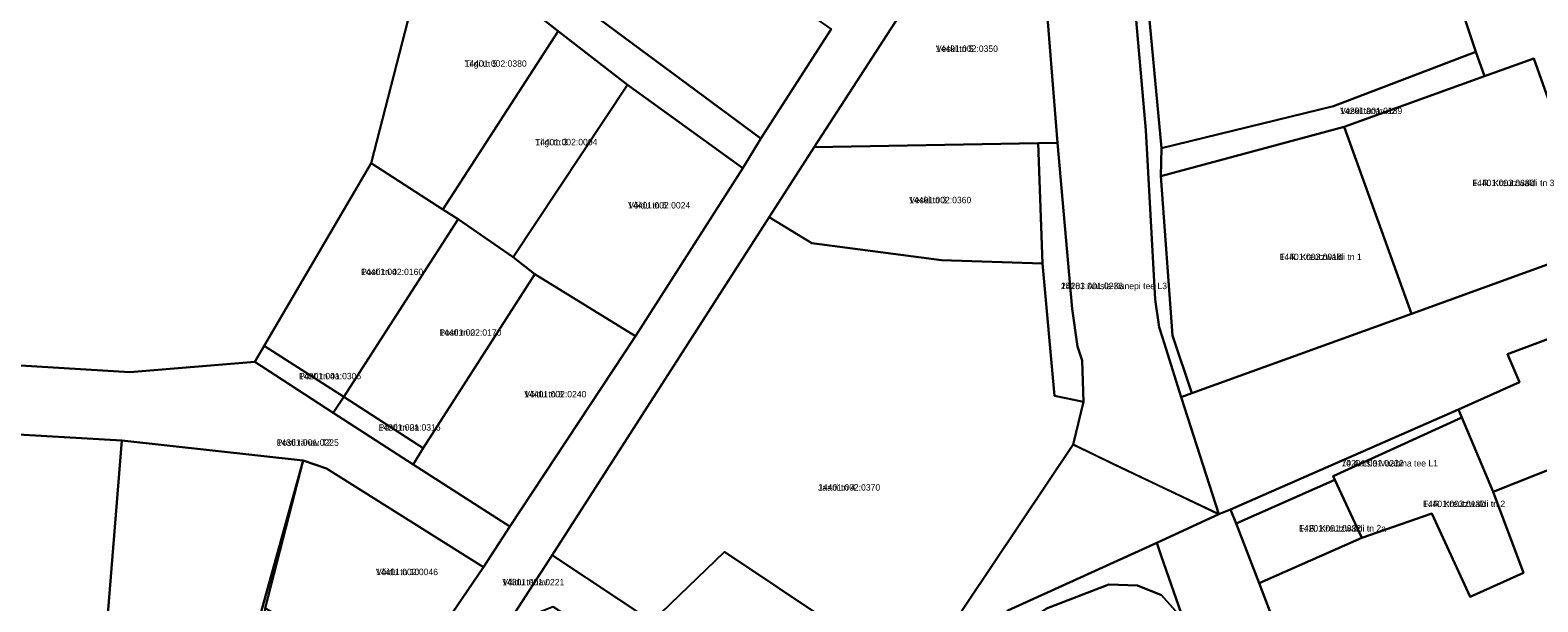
# Model space of a CAD drawing. Extents: x 640657 to 665127, y 6395726 to 6426831.
# Drawn here: x 649927.6 to 650279.7, y 6412496.8 to 6412630.2 of the extents above; entities that cross this region are included whole.
import ezdxf

# ---------------------------------------------------------------- set-up
doc = ezdxf.new("R2010")
doc.units = 0
for name, color, linetype in [('L_AADRESS', 7, 'Continuous'), ('PIIR', 7, 'Continuous'), ('TUNNUS', 7, 'Continuous')]:
    doc.layers.add(name, color=color, linetype=linetype)

msp = doc.modelspace()

# ---------------------------------------------------------------- linework, layer by layer
at = {"layer": 'PIIR'}
for points in [[(650237.63, 6412705.98), (650303.88, 6412730.75), (650316.1, 6412701.52), (650316.75, 6412691.86), (650305.68, 6412683.87), (650314.59, 6412660.95), (650328.64, 6412621.96), (650285.03, 6412605.8), (650278.75, 6412623.58), (650267.2, 6412619.43), (650265.16, 6412625.12), (650252.6, 6412662.9)], [(650196.38, 6412544.58), (650192.03, 6412558.48), (650191.24, 6412560.88), (650190.3, 6412567.31), (650188.12, 6412606.82), (650184.85, 6412644.1), (650184.49, 6412647.84), (650182.46, 6412660.87), (650180.97, 6412664.81), (650176.35, 6412683.53), (650172.79, 6412698.44), (650170.66, 6412706.52), (650172.47, 6412706.22), (650178.71, 6412684.02), (650184.97, 6412661.12), (650188.11, 6412641.75), (650191.8, 6412602.62), (650191.64, 6412596.08), (650194.33, 6412558.97), (650198.85, 6412545.44)], [(650050.88, 6412629.95), (650021.1, 6412653.3), (650025.2, 6412659.37), (650048.24, 6412643.28), (650061.58, 6412664.94), (650062.55, 6412666.63), (650063.83, 6412668.79), (650080.22, 6412694.46), (650083.6, 6412692.36), (650087.19, 6412691.13), (650069.2, 6412662.15), (650054.81, 6412636.95), (650098.19, 6412604.91), (650094.03, 6412597.95), (650067.08, 6412617.43)], [(650188.11, 6412641.75), (650252.6, 6412662.9), (650265.16, 6412625.12), (650231.95, 6412612.47), (650191.8, 6412602.62)], [(650069.2, 6412662.15), (650114.66, 6412630.41), (650098.19, 6412604.91), (650054.81, 6412636.95)], [(650007.16, 6412599.18), (650021.1, 6412653.3), (650050.88, 6412629.95), (650023.97, 6412588.36)], [(650110.64, 6412602.88), (650140.29, 6412648.7), (650164, 6412646.78), (650164.41, 6412641.93), (650167.51, 6412603.89), (650163, 6412603.82)], [(650050.88, 6412629.95), (650067.08, 6412617.43), (650040.38, 6412577.21), (650027.48, 6412586.05), (650023.97, 6412588.36)], [(650191.8, 6412602.62), (650231.95, 6412612.47), (650265.16, 6412625.12), (650267.2, 6412619.43), (650234.47, 6412607.65), (650191.64, 6412596.08)], [(650234.47, 6412607.65), (650267.2, 6412619.43), (650278.75, 6412623.58), (650285.03, 6412605.8), (650294.18, 6412579.92), (650250.19, 6412564)], [(650067.08, 6412617.43), (650094.03, 6412597.95), (650068.89, 6412558.76), (650045.39, 6412573.28), (650040.38, 6412577.21)], [(650191.64, 6412596.08), (650234.47, 6412607.65), (650250.19, 6412564), (650198.85, 6412545.44), (650194.33, 6412558.97)], [(650100.11, 6412586.58), (650110.64, 6412602.88), (650163, 6412603.82), (650163.98, 6412575.75), (650140.41, 6412576.53), (650110.12, 6412580.5)], [(650166.81, 6412544.84), (650163.98, 6412575.75), (650163, 6412603.82), (650167.51, 6412603.89), (650170.92, 6412565.14), (650172.19, 6412556.37), (650173.27, 6412553.13), (650173.59, 6412543.42)], [(649982.2, 6412556.55), (650007.16, 6412599.18), (650023.97, 6412588.36), (650027.48, 6412586.05), (650000.83, 6412544.61)], [(650000.83, 6412544.61), (650027.48, 6412586.05), (650040.38, 6412577.21), (650045.39, 6412573.28), (650019.36, 6412532.66)], [(650049.5, 6412507.64), (650100.11, 6412586.58), (650110.12, 6412580.5), (650140.41, 6412576.53), (650163.98, 6412575.75), (650166.81, 6412544.84), (650173.59, 6412543.42), (650171.18, 6412533.52), (650121.2, 6412458.89), (650101.64, 6412472.15), (650114.65, 6412491.83), (650089.68, 6412508.43), (650072.85, 6412492.16)], [(650017.02, 6412528.86), (650019.36, 6412532.66), (650045.39, 6412573.28), (650068.89, 6412558.76), (650039.58, 6412514.37)], [(649803.8, 6412545.57), (649803.8, 6412561.5), (649842.2, 6412558.3), (649880.4, 6412555), (649913.7, 6412552.6), (649950.8, 6412550.4), (649980.06, 6412552.77), (649998.34, 6412540.87), (650017.02, 6412528.86), (650039.58, 6412514.37), (650033.45, 6412504.9), (649996.8, 6412527.89), (649991.28, 6412529.73), (649949, 6412534.42), (649912.56, 6412536.54), (649879.16, 6412539.16), (649840.77, 6412542.38)], [(650261.17, 6412541.68), (650275.38, 6412548.01), (650272.55, 6412554.57), (650296.32, 6412563.42), (650306.65, 6412537.3), (650269.2, 6412522.44), (650261.95, 6412539.83)], [(649980.06, 6412552.77), (649982.2, 6412556.55), (650000.83, 6412544.61), (649998.34, 6412540.87)], [(649998.34, 6412540.87), (650000.83, 6412544.61), (650019.36, 6412532.66), (650017.02, 6412528.86)], [(650209.23, 6412515.05), (650207.86, 6412518.33), (650261.17, 6412541.68), (650261.95, 6412539.83), (650231.89, 6412526.1), (650232.22, 6412525.25)], [(650231.89, 6412526.1), (650261.95, 6412539.83), (650269.2, 6412522.44), (650276.32, 6412503.54), (650263.87, 6412497.98), (650254.9, 6412517.39), (650238.53, 6412511.75), (650232.22, 6412525.25)], [(649912.56, 6412536.54), (649949, 6412534.42), (649940.97, 6412435.19), (649916.45, 6412451.11), (649915.5, 6412479.78), (649914.89, 6412490.68)], [(650214.58, 6412501.13), (650238.53, 6412511.75), (650254.9, 6412517.39), (650263.87, 6412497.98), (650276.32, 6412503.54), (650269.2, 6412522.44), (650306.65, 6412537.3), (650314.94, 6412516.54), (650319.99, 6412504.57), (650323.98, 6412506.36), (650331.51, 6412487.45), (650289.44, 6412471.02), (650300.92, 6412441.95), (650264.14, 6412427.46), (650240.42, 6412486.98), (650223.07, 6412478.87)], [(649991.28, 6412529.74), (649964.86, 6412434.51), (649947.82, 6412430.62), (649940.46, 6412428.95), (649940.97, 6412435.19), (649949, 6412534.42)], [(649987.48, 6412247.25), (649993.04, 6412264.04), (650000.11, 6412275.95), (650001.42, 6412275.27), (650121.2, 6412458.89), (650171.18, 6412533.52), (650205.18, 6412517.21), (650190.65, 6412510.58), (650155.87, 6412494.77), (650009.35, 6412271.01), (650010.7, 6412270.29), (650001.36, 6412252.53)], [(649947.82, 6412430.62), (649964.86, 6412434.51), (649991.28, 6412529.74), (649982.46, 6412495.27), (649969.45, 6412433.87), (649961.58, 6412421.62)], [(649991.28, 6412529.74), (649996.8, 6412527.89), (650033.45, 6412504.9), (650013.94, 6412476.29), (649982.46, 6412495.27)], [(650214.58, 6412501.13), (650209.23, 6412515.05), (650232.22, 6412525.25), (650238.53, 6412511.75)], [(650190.65, 6412510.58), (650205.18, 6412517.21), (650207.86, 6412518.33), (650209.23, 6412515.05), (650214.58, 6412501.13), (650223.07, 6412478.87), (650245.23, 6412419.87), (650232.23, 6412414.69), (650213.7, 6412462.5), (650194.7, 6412456.6), (650185.6, 6412477.4), (650199.7, 6412484.5), (650196.89, 6412492.57), (650191.7, 6412507.5)], [(650155.87, 6412494.77), (650190.65, 6412510.58), (650191.7, 6412507.5), (650196.89, 6412492.57), (650191.74, 6412498.37), (650186.18, 6412500.59), (650179.5, 6412500.79), (650164.95, 6412495.21), (650158.1, 6412490.46), (650150.4, 6412481.42), (650125.77, 6412443.98), (650107.47, 6412415.68), (650089.5, 6412388.38), (650069.58, 6412357.95), (650051.89, 6412331.42), (650028.46, 6412296.89), (650029.34, 6412293.8), (650015.32, 6412267.89), (650010.22, 6412255.95), (650001.36, 6412252.53), (650010.7, 6412270.29), (650009.35, 6412271.01)], [(650072.85, 6412492.16), (650089.68, 6412508.43), (650114.65, 6412491.83), (650101.64, 6412472.15)], [(650038.91, 6412491.36), (650049.5, 6412507.64), (650072.85, 6412492.16), (650101.64, 6412472.15), (650121.2, 6412458.89), (650115.7, 6412451.99), (650113.86, 6412453.15), (650065.87, 6412485.05), (650049.72, 6412495.59)], [(650150.4, 6412481.42), (650158.1, 6412490.46), (650164.95, 6412495.21), (650179.5, 6412500.79), (650186.18, 6412500.59), (650191.74, 6412498.37), (650196.89, 6412492.57), (650199.7, 6412484.5), (650185.6, 6412477.4), (650194.7, 6412456.6), (650213.7, 6412462.5), (650232.23, 6412414.69), (650191.62, 6412398.42), (650192.44, 6412455.02)]]:
    msp.add_lwpolyline(points, close=True, dxfattribs=at)
for points in [[(650021.1, 6412653.3), (650007.16, 6412599.18), (649982.2, 6412556.55), (649980.06, 6412552.77), (649950.8, 6412550.4), (649913.7, 6412552.6), (649880.4, 6412555), (649842.2, 6412558.3), (649803.8, 6412561.5), (649798.2, 6412604.7), (649792.4, 6412645.6)], [(650523.13, 6412650.87), (650462.26, 6412625.96), (650436.76, 6412616.5), (650407.09, 6412605.56), (650391.78, 6412599.81), (650355.46, 6412586.17), (650329.82, 6412576.39), (650296.32, 6412563.42), (650272.55, 6412554.57), (650275.38, 6412548.01), (650261.17, 6412541.68), (650207.86, 6412518.33), (650205.18, 6412517.21), (650196.38, 6412544.58), (650198.85, 6412545.44), (650250.19, 6412564), (650294.18, 6412579.92), (650340.27, 6412596.89), (650386.32, 6412614.06), (650401.68, 6412620.02), (650443.31, 6412635.66)], [(650140.29, 6412648.7), (650110.64, 6412602.88), (650100.11, 6412586.58), (650049.5, 6412507.64), (650038.91, 6412491.36)], [(650184.85, 6412644.1), (650188.12, 6412606.82), (650190.3, 6412567.31), (650191.24, 6412560.88), (650192.03, 6412558.48), (650196.38, 6412544.58), (650205.18, 6412517.21), (650180.8, 6412528.79), (650171.18, 6412533.52), (650173.59, 6412543.42), (650173.27, 6412553.13), (650172.19, 6412556.37), (650170.92, 6412565.14), (650167.51, 6412603.89), (650164.41, 6412641.93)], [(650013.94, 6412476.29), (650033.45, 6412504.9), (650039.58, 6412514.37), (650068.89, 6412558.76), (650094.03, 6412597.95), (650098.19, 6412604.91), (650114.66, 6412630.41)]]:
    msp.add_lwpolyline(points, dxfattribs=at)

# ---------------------------------------------------------------- texts
at = {"layer": 'L_AADRESS'}
for s, p in [('Veski tn 5', (650139.07, 6412625.11)), ('Tiigi tn 5', (650029.02, 6412621.63)), ('Veski tänav J2', (650233.5, 6412610.6)), ('Tiigi tn 3', (650045.52, 6412603.32)), ('F. R. Kreutzwaldi tn 3', (650264.37, 6412593.79)), ('Võidu tn 6', (650067.21, 6412588.57)), ('Veski tn 3', (650132.84, 6412589.79)), ('F. R. Kreutzwaldi tn 1', (650219.36, 6412576.54)), ('Posti tn 4', (650004.84, 6412573.03)), ('25183 Antsla-Kanepi tee L3', (650168.3, 6412569.75)), ('Posti tn 2', (650023.11, 6412558.88)), ('Posti tn 4a', (649990.36, 6412548.71)), ('Võidu tn 8', (650042.96, 6412544.48)), ('Posti tn 2a', (650008.91, 6412536.74)), ('Posti tänav T2', (649985.13, 6412533.2)), ('70 Antsla-Vaabina tee L1', (650233.81, 6412528.37)), ('Jaani tn 4', (650111.57, 6412522.74)), ('F. R. Kreutzwaldi tn 2', (650252.86, 6412518.9)), ('F. R. Kreutzwaldi tn 2a', (650223.9, 6412513.19)), ('Võidu tn 10', (650008.3, 6412503.01)), ('Võidu tänav', (650037.81, 6412500.63))]:
    msp.add_text(s, height=1.5, dxfattribs=at).set_placement(p)
at = {"layer": 'TUNNUS'}
for s, p in [('14401:002:0350', (650139.07, 6412625.11)), ('14401:002:0380', (650029.02, 6412621.63)), ('14201:001:0189', (650233.5, 6412610.6)), ('14401:002:0004', (650045.52, 6412603.32)), ('14401:003:0380', (650264.37, 6412593.79)), ('14401:002:0024', (650067.21, 6412588.57)), ('14401:002:0360', (650132.84, 6412589.79)), ('14401:003:0018', (650219.36, 6412576.54)), ('14401:002:0160', (650004.84, 6412573.03)), ('14201:001:0236', (650168.3, 6412569.75)), ('14401:002:0170', (650023.11, 6412558.88)), ('14201:001:0306', (649990.36, 6412548.71)), ('14401:002:0240', (650042.96, 6412544.48)), ('14201:001:0316', (650008.91, 6412536.74)), ('14301:001:0225', (649985.13, 6412533.2)), ('14201:001:0232', (650233.81, 6412528.37)), ('14401:002:0370', (650111.57, 6412522.74)), ('14401:003:0130', (650252.86, 6412518.9)), ('14201:001:0332', (650223.9, 6412513.19)), ('14401:002:0046', (650008.3, 6412503.01)), ('14301:001:0221', (650037.81, 6412500.63))]:
    msp.add_text(s, height=1.5, dxfattribs=at).set_placement(p)

doc.saveas('drawing.dxf')
